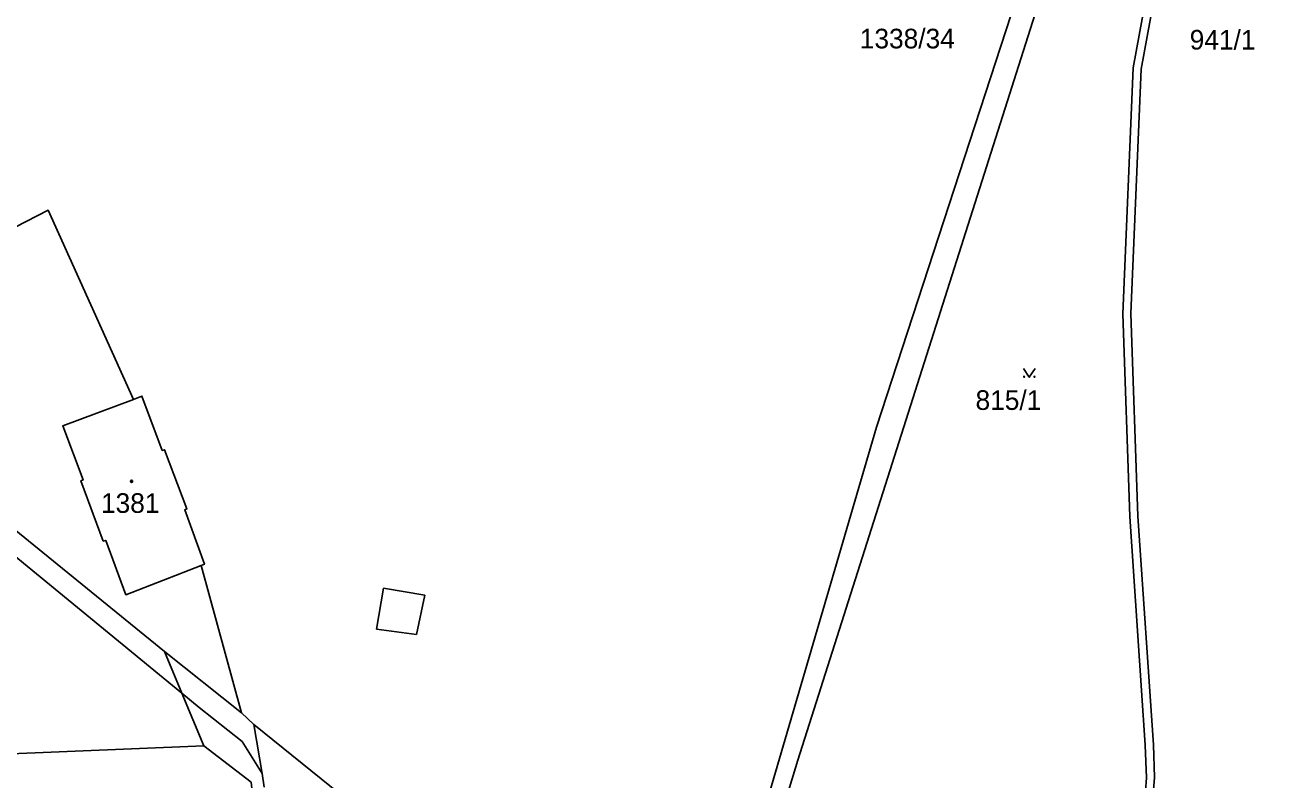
# Model space of a CAD drawing. Extents: x -598934 to -598196, y -1162208 to -1161502.
# Drawn here: x -598382.2 to -598274, y -1161978.6 to -1161913.2 of the extents above; entities that cross this region are included whole.
import ezdxf

# ---------------------------------------------------------------- set-up
doc = ezdxf.new("R2010")
doc.units = 0
for name, color, linetype in [('KN_CAR_KR', 7, 'Continuous'), ('KN_KULTURY', 7, 'Continuous'), ('KN_PARC_CIS_POM', 7, 'Continuous'), ('KN_PARC_CIS_POZ', 7, 'Continuous'), ('KN_PARC_CIS_STAV', 7, 'Continuous'), ('KN_PARC_PLOCHA', 7, 'Continuous'), ('parcely_l', 7, 'Continuous')]:
    doc.layers.add(name, color=color, linetype=linetype)

msp = doc.modelspace()

# ---------------------------------------------------------------- linework, layer by layer
at = {"layer": 'KN_CAR_KR'}
for points in [[(-598280.58, -1161889.1), (-598285.73, -1161917.07)], [(-598285.73, -1161917.07), (-598286.61, -1161938.22)], [(-598286.61, -1161938.22), (-598286, -1161955.73)], [(-598396.26, -1161948.42), (-598368.68, -1161971.07)], [(-598286, -1161955.73), (-598284.66, -1161975.54)], [(-598351.84, -1161965.53), (-598351.24, -1161961.98)], [(-598351.24, -1161961.98), (-598347.66, -1161962.59)], [(-598347.66, -1161962.59), (-598348.38, -1161965.99)], [(-598348.38, -1161965.99), (-598351.84, -1161965.53)], [(-598368.68, -1161971.07), (-598367.17, -1161972.31)], [(-598367.17, -1161972.31), (-598363.46, -1161975.23)], [(-598362.46, -1161973.78), (-598363.52, -1161972.77)], [(-598362.46, -1161973.78), (-598361.74, -1161978)], [(-598330.34, -1161999.7), (-598362.46, -1161973.78)], [(-598363.46, -1161975.23), (-598361.74, -1161978)], [(-598284.66, -1161975.54), (-598284.56, -1161978.37)], [(-598361.74, -1161978), (-598361.55, -1161979.19)], [(-598284.56, -1161978.37), (-598284.98, -1161983.3)]]:
    msp.add_lwpolyline(points, dxfattribs=at)
at = {"layer": 'KN_KULTURY'}
msp.add_lwpolyline([(-598295.89, -1161942.98), (-598295.39, -1161943.73), (-598294.89, -1161942.98)], dxfattribs=at)
for centre, radius in [((-598295.84, -1161943.68), 0.05), ((-598294.94, -1161943.68), 0.05), ((-598373.02, -1161952.73), 0.09), ((-598373.02, -1161952.73), 0.0398)]:
    msp.add_circle(centre, radius, dxfattribs=at)
at = {"layer": 'KN_PARC_PLOCHA'}
for points in [[(-598288.1, -1161990.75), (-598322.07, -1161998.71), (-598315.42, -1161976.86), (-598294.91, -1161912.37), (-598291.89, -1161903.62), (-598286.96, -1161891.51), (-598272.85, -1161861.26), (-598271.79, -1161860.57), (-598281.27, -1161888.97), (-598286.42, -1161916.94), (-598287.31, -1161938.24), (-598286.7, -1161955.76), (-598285.36, -1161975.57), (-598285.26, -1161978.39), (-598285.61, -1161982.99)], [(-598367, -1161960.01), (-598373.51, -1161962.55), (-598375.25, -1161957.84), (-598375.47, -1161957.9), (-598377.41, -1161952.68), (-598377.22, -1161952.61), (-598378.97, -1161947.93), (-598372.86, -1161945.64), (-598372.13, -1161945.36), (-598370.37, -1161950.06), (-598370.17, -1161949.99), (-598368.24, -1161955.12), (-598368.43, -1161955.19), (-598366.72, -1161959.9)]]:
    msp.add_lwpolyline(points, close=True, dxfattribs=at)
for points in [[(-598285.61, -1161982.99), (-598285.26, -1161978.39), (-598285.36, -1161975.57), (-598286.7, -1161955.76), (-598287.31, -1161938.24), (-598286.42, -1161916.94), (-598281.27, -1161888.97)], [(-598294.91, -1161912.37), (-598315.42, -1161976.86), (-598322.07, -1161998.71), (-598288.1, -1161990.75), (-598289.55, -1161993.5), (-598321.37, -1162000.94), (-598325.91, -1162001.7), (-598328.9, -1162001.67), (-598330.87, -1162001.34), (-598330.34, -1161999.7), (-598330.42, -1161999.13), (-598329.17, -1161999.67), (-598327.84, -1161999.87), (-598326.6, -1161999.69), (-598325.46, -1161999.37), (-598324.63, -1161998.8), (-598323.76, -1161998.16), (-598323.03, -1161997.13), (-598322.64, -1161996.12), (-598321.28, -1161991.38), (-598308.6, -1161948.05), (-598296.97, -1161912.35)], [(-598296.97, -1161912.35), (-598308.6, -1161948.05), (-598321.28, -1161991.38)], [(-598432.57, -1161916.66), (-598370.19, -1161967.44), (-598368.68, -1161971.07), (-598366.78, -1161975.62), (-598390.45, -1161976.59)], [(-598388.87, -1161933.7), (-598380.24, -1161929.28), (-598372.86, -1161945.64), (-598378.97, -1161947.93), (-598377.22, -1161952.61), (-598377.41, -1161952.68), (-598375.47, -1161957.9), (-598375.25, -1161957.84), (-598373.51, -1161962.55), (-598367, -1161960.01), (-598363.52, -1161972.77), (-598370.19, -1161967.44), (-598432.57, -1161916.66)], [(-598362.68, -1161978.77), (-598366.78, -1161975.62), (-598368.68, -1161971.07), (-598370.19, -1161967.44), (-598363.52, -1161972.77), (-598367, -1161960.01), (-598366.72, -1161959.9), (-598368.43, -1161955.19), (-598368.24, -1161955.12), (-598370.17, -1161949.99), (-598370.37, -1161950.06), (-598372.13, -1161945.36), (-598372.86, -1161945.64), (-598380.24, -1161929.28), (-598388.87, -1161933.7)], [(-598390.45, -1161976.59), (-598366.78, -1161975.62), (-598362.68, -1161978.77), (-598361.9, -1161985.65), (-598369.78, -1161985.86), (-598381.89, -1161986.93), (-598393.12, -1161991.3)]]:
    msp.add_lwpolyline(points, dxfattribs=at)
at = {"layer": 'parcely_l'}
for points in [[(-598288.1, -1161990.75), (-598322.07, -1161998.71), (-598315.42, -1161976.86), (-598294.91, -1161912.37), (-598291.89, -1161903.62), (-598286.96, -1161891.51), (-598272.85, -1161861.26), (-598271.79, -1161860.57)], [(-598271.79, -1161860.57), (-598281.27, -1161888.97), (-598286.42, -1161916.94), (-598287.31, -1161938.24), (-598286.7, -1161955.76), (-598285.36, -1161975.57), (-598285.26, -1161978.39), (-598285.61, -1161982.99), (-598288.1, -1161990.75)], [(-598295.82, -1161909.22), (-598296.97, -1161912.35), (-598308.6, -1161948.05), (-598321.28, -1161991.38), (-598322.64, -1161996.12), (-598323.03, -1161997.13), (-598323.76, -1161998.16), (-598324.63, -1161998.8), (-598325.46, -1161999.37), (-598326.6, -1161999.69), (-598327.84, -1161999.87), (-598329.17, -1161999.67), (-598330.42, -1161999.13), (-598330.34, -1161999.7), (-598330.87, -1162001.34)], [(-598370.19, -1161967.44), (-598432.57, -1161916.66)], [(-598372.86, -1161945.64), (-598380.24, -1161929.28), (-598388.87, -1161933.7)], [(-598372.86, -1161945.64), (-598378.97, -1161947.93), (-598377.22, -1161952.61), (-598377.41, -1161952.68), (-598375.47, -1161957.9), (-598375.25, -1161957.84), (-598373.51, -1161962.55), (-598367, -1161960.01)], [(-598367, -1161960.01), (-598366.72, -1161959.9), (-598368.43, -1161955.19), (-598368.24, -1161955.12), (-598370.17, -1161949.99), (-598370.37, -1161950.06), (-598372.13, -1161945.36), (-598372.86, -1161945.64)], [(-598370.19, -1161967.44), (-598363.52, -1161972.77), (-598367, -1161960.01)], [(-598410.61, -1161961.27), (-598390.45, -1161976.59), (-598366.78, -1161975.62)], [(-598366.78, -1161975.62), (-598368.68, -1161971.07), (-598370.19, -1161967.44)], [(-598361.9, -1161985.65), (-598362.68, -1161978.77), (-598366.78, -1161975.62)]]:
    msp.add_lwpolyline(points, dxfattribs=at)

# ---------------------------------------------------------------- texts
at = {"layer": 'KN_PARC_CIS_POM'}
msp.add_text('941/1', height=1.7, dxfattribs=at).set_placement((-598281.52, -1161915.37))
at = {"layer": 'KN_PARC_CIS_POZ'}
msp.add_text('815/1', height=1.7, dxfattribs=at).set_placement((-598300.04, -1161946.55))
at = {"layer": 'KN_PARC_CIS_STAV'}
for s, p in [('1338/34', (-598310.05, -1161915.27)), ('1381', (-598375.67, -1161955.46))]:
    msp.add_text(s, height=1.7, dxfattribs=at).set_placement(p)

doc.saveas('drawing.dxf')
